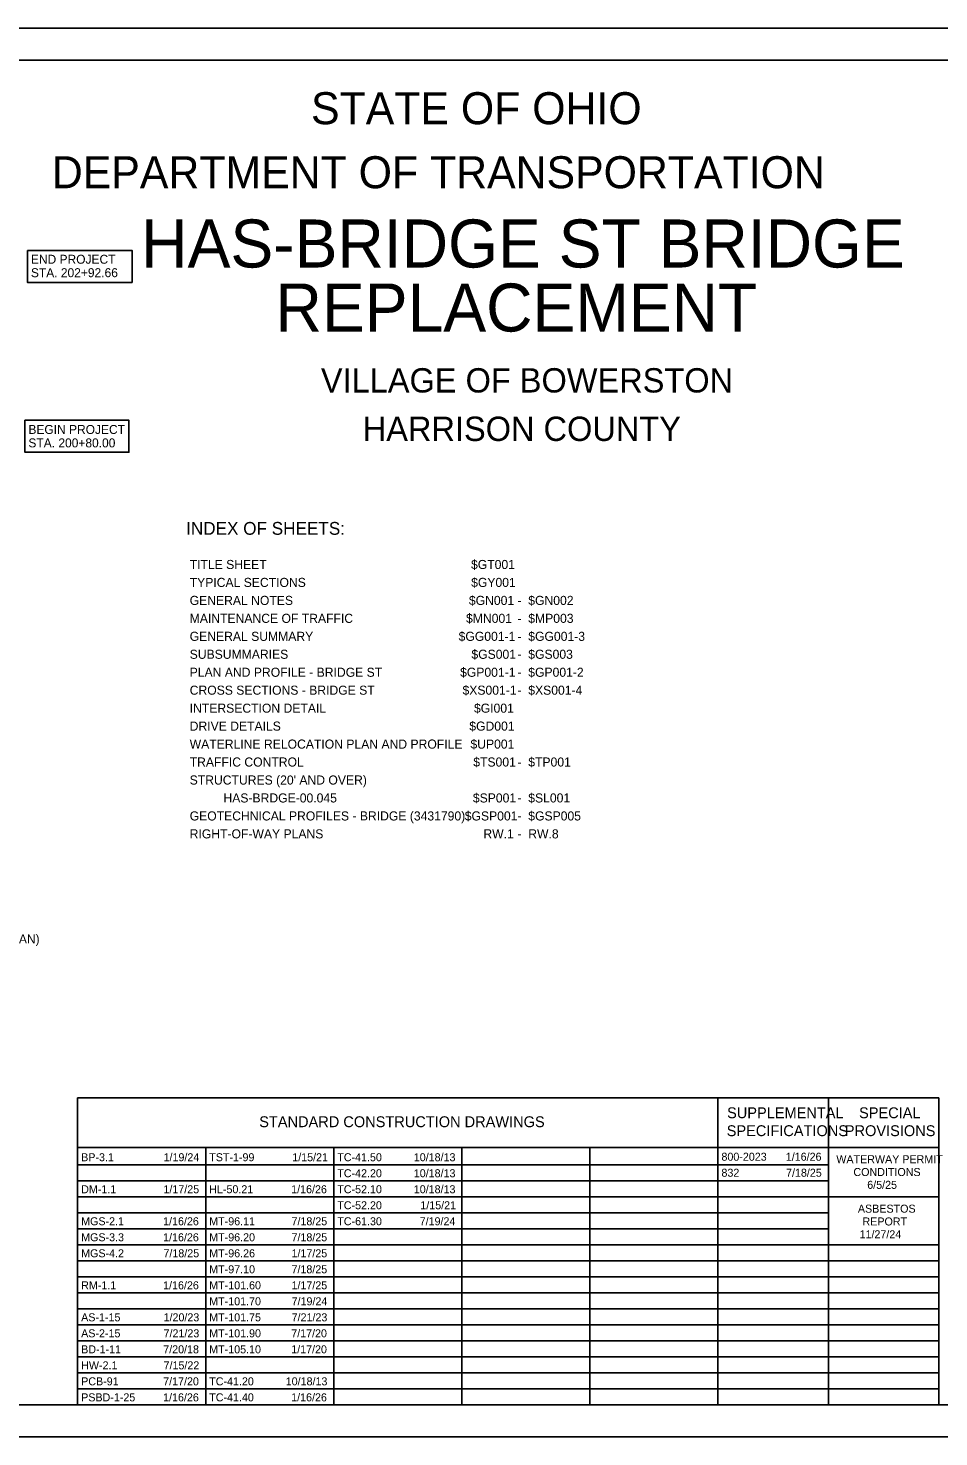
# Model space of a CAD drawing. Extents: x -7.1 to 34, y 0 to 22.
# Drawn here: x 9.38 to 23.6, y 0 to 22 of the extents above; entities that cross this region are included whole.
import ezdxf

# ---------------------------------------------------------------- set-up
doc = ezdxf.new("R2010")
doc.units = 0
for name, color, linetype in [('SH_Border', 7, 'Continuous'), ('SH_Cut_Line', 7, 'Continuous'), ('SH_Data', 7, 'Continuous'), ('SH_Text', 7, 'Continuous')]:
    doc.layers.add(name, color=color, linetype=linetype)

msp = doc.modelspace()

# ---------------------------------------------------------------- linework, layer by layer
at = {"layer": 'SH_Border'}
msp.add_lwpolyline([(1.5, 21.5), (33.5, 21.5), (33.5, 0.5), (1.5, 0.5)], close=True, dxfattribs=at)
at = {"layer": 'SH_Cut_Line'}
msp.add_lwpolyline([(0, 0), (34, 0), (34, 22), (0, 22)], close=True, dxfattribs=at)
at = {"layer": 'SH_Data'}
for p, q in [((10.15, 5.292), (23.6, 5.292)), ((10.15, 0.5), (10.15, 5.292)), ((20.15, 0.5), (20.15, 5.292)), ((21.875, 0.5), (21.875, 5.292)), ((23.6, 0.5), (23.6, 5.292)), ((10.15, 4.521), (23.6, 4.521)), ((12.15, 0.5), (12.15, 4.521)), ((14.15, 0.5), (14.15, 4.521)), ((16.15, 0.5), (16.15, 4.521)), ((18.15, 0.5), (18.15, 4.521)), ((10.15, 4.25), (21.875, 4.25)), ((10.15, 4), (21.875, 4)), ((10.15, 3.75), (23.6, 3.75)), ((10.15, 3.5), (21.875, 3.5)), ((10.15, 3.25), (21.875, 3.25)), ((10.15, 3), (23.6, 3)), ((10.15, 2.75), (23.6, 2.75)), ((10.15, 2.5), (23.6, 2.5)), ((10.15, 2.25), (23.6, 2.25)), ((10.15, 2), (23.6, 2)), ((10.15, 1.75), (23.6, 1.75)), ((10.15, 1.5), (23.6, 1.5)), ((10.15, 1.25), (23.6, 1.25)), ((10.15, 1), (23.6, 1)), ((10.15, 0.75), (23.6, 0.75))]:
    msp.add_line(p, q, dxfattribs=at)
at = {"layer": 'SH_Text'}
for points in [[(9.365, 18.529), (10.999, 18.529), (10.999, 18.029), (9.365, 18.029)], [(9.326, 15.877), (10.95, 15.877), (10.95, 15.377), (9.326, 15.377)]]:
    msp.add_lwpolyline(points, close=True, dxfattribs=at)

# ---------------------------------------------------------------- texts
for s, height, p in [('STATE OF OHIO', 0.5, (13.795, 20.5)), ('DEPARTMENT OF TRANSPORTATION', 0.5, (9.747, 19.5)), ('HAS-BRIDGE ST BRIDGE', 0.75, (11.143, 18.262)), ('END PROJECT', 0.14, (9.42, 18.321)), ('STA. 202+92.66', 0.14, (9.42, 18.111)), ('REPLACEMENT', 0.75, (13.241, 17.262)), ('VILLAGE OF BOWERSTON', 0.38, (13.949, 16.31)), ('HARRISON COUNTY', 0.38, (14.603, 15.553)), ('BEGIN PROJECT', 0.14, (9.381, 15.663)), ('STA. 200+80.00', 0.14, (9.381, 15.453)), ('INDEX OF SHEETS:', 0.2, (11.844, 14.088)), ('TITLE SHEET', 0.14193, (11.9, 13.553)), ('$GT001', 0.1419, (16.294, 13.553)), ('$GY001', 0.1419, (16.296, 13.273)), ('TYPICAL SECTIONS', 0.14193, (11.9, 13.273)), ('GENERAL NOTES', 0.14193, (11.9, 12.992)), ('$GN001', 0.1419, (16.261, 12.992)), ('-', 0.142, (17.02, 12.992)), ('$GN002', 0.1419, (17.188, 12.992)), ('MAINTENANCE OF TRAFFIC', 0.14193, (11.9, 12.712)), ('$MN001', 0.1419, (16.216, 12.712)), ('-', 0.142, (17.02, 12.712)), ('$MP003', 0.1419, (17.188, 12.712)), ('GENERAL SUMMARY', 0.14193, (11.9, 12.431)), ('$GG001-1', 0.1419, (16.1, 12.431)), ('$GG001-3', 0.1419, (17.188, 12.431)), ('-', 0.142, (17.02, 12.431)), ('SUBSUMMARIES', 0.14193, (11.9, 12.151)), ('$GS001', 0.1419, (16.3, 12.151)), ('-', 0.142, (17.02, 12.151)), ('$GS003', 0.1419, (17.188, 12.151)), ('PLAN AND PROFILE - BRIDGE ST', 0.14193, (11.9, 11.87)), ('$GP001-1', 0.1419, (16.123, 11.87)), ('-', 0.142, (17.02, 11.87)), ('$GP001-2', 0.1419, (17.188, 11.87)), ('CROSS SECTIONS - BRIDGE ST', 0.14193, (11.9, 11.59)), ('$XS001-1', 0.1419, (16.161, 11.59)), ('$XS001-4', 0.1419, (17.188, 11.59)), ('INTERSECTION DETAIL', 0.14193, (11.9, 11.309)), ('$GI001', 0.1419, (16.34, 11.309)), ('-', 0.142, (17.02, 11.59)), ('DRIVE DETAILS', 0.14193, (11.9, 11.029)), ('$GD001', 0.1419, (16.267, 11.029)), ('WATERLINE RELOCATION PLAN AND PROFILE', 0.14193, (11.9, 10.748)), ('$UP001', 0.1419, (16.285, 10.748)), ('TRAFFIC CONTROL', 0.14193, (11.9, 10.468)), ('$TS001', 0.1419, (16.329, 10.468)), ('$TP001', 0.1419, (17.188, 10.468)), ('-', 0.142, (17.02, 10.468)), ("STRUCTURES (20' AND OVER)", 0.14193, (11.9, 10.187)), ('          HAS-BRDGE-00.045', 0.14193, (11.9, 9.907)), ('$SP001', 0.1419, (16.323, 9.907)), ('-', 0.142, (17.02, 9.907)), ('$SL001', 0.1419, (17.188, 9.907)), ('GEOTECHNICAL PROFILES - BRIDGE (3431790)', 0.14193, (11.9, 9.626)), ('$GSP001', 0.1419, (16.196, 9.626)), ('-', 0.142, (17.02, 9.626)), ('$GSP005', 0.1419, (17.188, 9.626)), ('RIGHT-OF-WAY PLANS', 0.14193, (11.9, 9.346)), ('RW.1', 0.1419, (16.487, 9.346)), ('RW.8', 0.1419, (17.188, 9.346)), ('-', 0.142, (17.02, 9.346)), ('07 - LOCAL (URBAN)', 0.14, (7.735, 7.706)), ('SUPPLEMENTAL', 0.17, (20.293, 4.976)), ('SPECIAL', 0.17, (22.354, 4.976)), ('STANDARD CONSTRUCTION DRAWINGS', 0.17, (12.986, 4.836)), ('SPECIFICATIONS', 0.17, (20.287, 4.696)), ('PROVISIONS', 0.17, (22.132, 4.696)), ('BP-3.1', 0.125, (10.205, 4.304)), ('1/19/24', 0.125, (11.492, 4.304)), ('TST-1-99', 0.125, (12.205, 4.304)), ('1/15/21', 0.125, (13.502, 4.304)), ('TC-41.50', 0.125, (14.205, 4.304)), ('10/18/13', 0.125, (15.4, 4.304)), ('800-2023', 0.125, (20.205, 4.312)), ('1/16/26', 0.125, (21.21, 4.312)), ('TC-42.20', 0.125, (14.205, 4.054)), ('10/18/13', 0.125, (15.4, 4.054)), ('832', 0.125, (20.205, 4.062)), ('7/18/25', 0.125, (21.214, 4.062)), ('WATERWAY PERMIT', 0.125, (21.999, 4.273)), ('CONDITIONS', 0.125, (22.266, 4.073)), ('6/5/25', 0.125, (22.482, 3.873)), ('DM-1.1', 0.125, (10.205, 3.804)), ('1/17/25', 0.125, (11.49, 3.804)), ('HL-50.21', 0.125, (12.205, 3.804)), ('1/16/26', 0.125, (13.485, 3.804)), ('TC-52.10', 0.125, (14.205, 3.804)), ('10/18/13', 0.125, (15.4, 3.804)), ('TC-52.20', 0.125, (14.205, 3.554)), ('1/15/21', 0.125, (15.502, 3.554)), ('ASBESTOS', 0.125, (22.336, 3.501)), ('MGS-2.1', 0.125, (10.205, 3.304)), ('1/16/26', 0.125, (11.485, 3.304)), ('MT-96.11', 0.125, (12.205, 3.304)), ('7/18/25', 0.125, (13.49, 3.304)), ('TC-61.30', 0.125, (14.205, 3.304)), ('7/19/24', 0.125, (15.492, 3.304)), ('REPORT', 0.125, (22.408, 3.301)), ('MGS-3.3', 0.125, (10.205, 3.054)), ('1/16/26', 0.125, (11.485, 3.054)), ('MT-96.20', 0.125, (12.205, 3.054)), ('7/18/25', 0.125, (13.49, 3.054)), ('11/27/24', 0.125, (22.362, 3.101)), ('MGS-4.2', 0.125, (10.205, 2.804)), ('7/18/25', 0.125, (11.49, 2.804)), ('MT-96.26', 0.125, (12.205, 2.804)), ('1/17/25', 0.125, (13.49, 2.804)), ('MT-97.10', 0.125, (12.205, 2.554)), ('7/18/25', 0.125, (13.49, 2.554)), ('RM-1.1', 0.125, (10.205, 2.304)), ('1/16/26', 0.125, (11.485, 2.304)), ('MT-101.60', 0.125, (12.205, 2.304)), ('1/17/25', 0.125, (13.49, 2.304)), ('MT-101.70', 0.125, (12.205, 2.054)), ('7/19/24', 0.125, (13.492, 2.054)), ('AS-1-15', 0.125, (10.205, 1.804)), ('1/20/23', 0.125, (11.492, 1.804)), ('MT-101.75', 0.125, (12.205, 1.804)), ('7/21/23', 0.125, (13.492, 1.804)), ('AS-2-15', 0.125, (10.205, 1.554)), ('7/21/23', 0.125, (11.492, 1.554)), ('MT-101.90', 0.125, (12.205, 1.554)), ('7/17/20', 0.125, (13.486, 1.554)), ('BD-1-11', 0.125, (10.205, 1.304)), ('7/20/18', 0.125, (11.487, 1.304)), ('MT-105.10', 0.125, (12.205, 1.304)), ('1/17/20', 0.125, (13.486, 1.304)), ('HW-2.1', 0.125, (10.205, 1.054)), ('7/15/22', 0.125, (11.492, 1.054)), ('PCB-91', 0.125, (10.205, 0.804)), ('7/17/20', 0.125, (11.486, 0.804)), ('TC-41.20', 0.125, (12.205, 0.804)), ('10/18/13', 0.125, (13.4, 0.804)), ('PSBD-1-25', 0.125, (10.205, 0.554)), ('1/16/26', 0.125, (11.485, 0.554)), ('TC-41.40', 0.125, (12.205, 0.554)), ('1/16/26', 0.125, (13.485, 0.554))]:
    msp.add_text(s, height=height, dxfattribs=at).set_placement(p)

doc.saveas('drawing.dxf')
